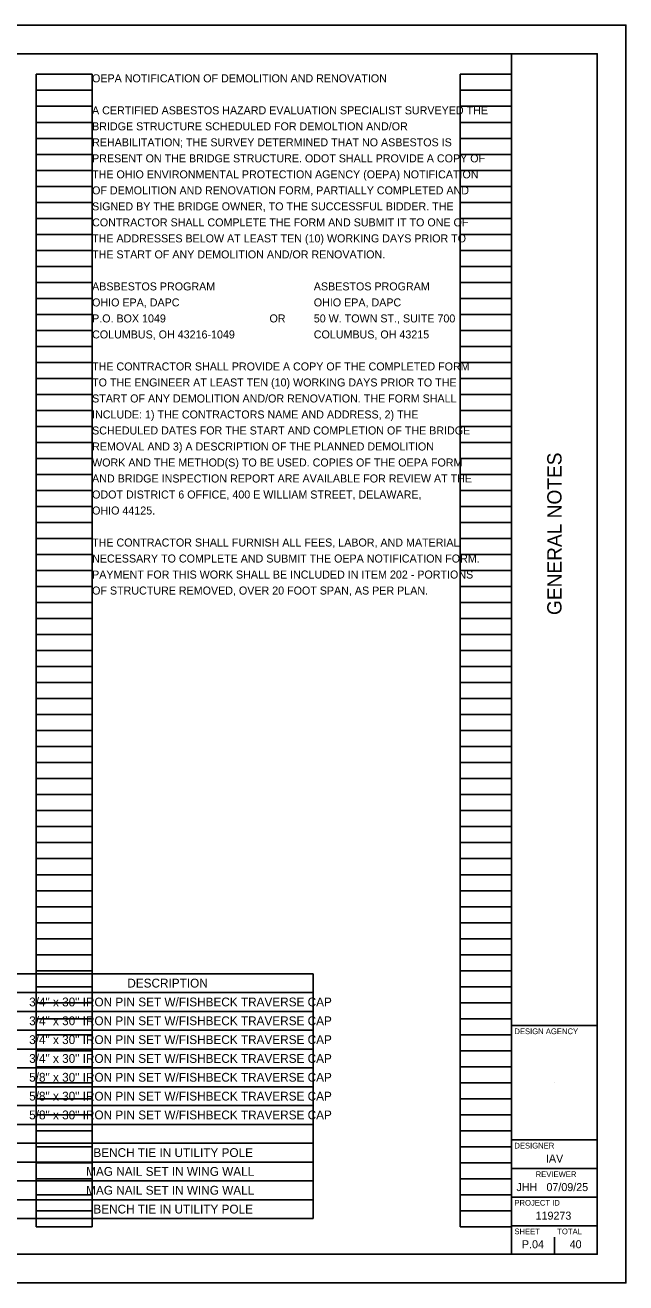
# Model space of a CAD drawing. Extents: x -10.1 to 34, y -4.5 to 22.
# Drawn here: x 23.49 to 34, y 0 to 22 of the extents above; entities that cross this region are included whole.
import ezdxf

# ---------------------------------------------------------------- set-up
doc = ezdxf.new("R2010")
doc.units = 0
for name, color, linetype in [('Default', 7, 'Continuous'), ('SH_Border', 7, 'Continuous'), ('SH_Cut_Line', 7, 'Continuous'), ('SH_Data', 7, 'Continuous'), ('SH_Text', 7, 'Continuous')]:
    doc.layers.add(name, color=color, linetype=linetype)

msp = doc.modelspace()

# ---------------------------------------------------------------- linework, layer by layer
at = {"layer": 'Default'}
for p, q in [((18.251, 5.407), (28.529, 5.407)), ((28.529, 5.407), (28.529, 1.125)), ((18.251, 5.078), (28.529, 5.078)), ((18.251, 4.749), (28.529, 4.749)), ((18.251, 4.419), (28.529, 4.419)), ((18.251, 4.09), (28.529, 4.09)), ((18.251, 3.76), (28.529, 3.76)), ((18.251, 3.431), (28.529, 3.431)), ((18.251, 3.102), (28.529, 3.102)), ((18.251, 2.772), (28.529, 2.772)), ((18.251, 2.443), (28.529, 2.443)), ((18.251, 2.113), (28.529, 2.113)), ((18.251, 1.784), (28.529, 1.784)), ((18.251, 1.454), (28.529, 1.454)), ((18.251, 1.125), (28.529, 1.125))]:
    msp.add_line(p, q, dxfattribs=at)
at = {"layer": 'SH_Cut_Line'}
for p, q in [((23.68, 0.98), (23.68, 21.14)), ((23.68, 21.14), (24.66, 21.14)), ((24.66, 0.98), (24.66, 21.14)), ((31.1, 0.98), (31.1, 21.14)), ((31.1, 21.14), (32, 21.14)), ((32, 0.98), (32, 21.14)), ((23.68, 20.86), (24.66, 20.86)), ((31.1, 20.86), (32, 20.86)), ((23.68, 20.58), (24.66, 20.58)), ((31.1, 20.58), (32, 20.58)), ((23.68, 20.3), (24.66, 20.3)), ((31.1, 20.3), (32, 20.3)), ((23.68, 20.02), (24.66, 20.02)), ((31.1, 20.02), (32, 20.02)), ((23.68, 19.74), (24.66, 19.74)), ((31.1, 19.74), (32, 19.74)), ((23.68, 19.46), (24.66, 19.46)), ((31.1, 19.46), (32, 19.46)), ((23.68, 19.18), (24.66, 19.18)), ((31.1, 19.18), (32, 19.18)), ((23.68, 18.9), (24.66, 18.9)), ((31.1, 18.9), (32, 18.9)), ((23.68, 18.62), (24.66, 18.62)), ((31.1, 18.62), (32, 18.62)), ((23.68, 18.34), (24.66, 18.34)), ((31.1, 18.34), (32, 18.34)), ((23.68, 18.06), (24.66, 18.06)), ((31.1, 18.06), (32, 18.06)), ((23.68, 17.78), (24.66, 17.78)), ((31.1, 17.78), (32, 17.78)), ((23.68, 17.5), (24.66, 17.5)), ((31.1, 17.5), (32, 17.5)), ((23.68, 17.22), (24.66, 17.22)), ((31.1, 17.22), (32, 17.22)), ((23.68, 16.94), (24.66, 16.94)), ((31.1, 16.94), (32, 16.94)), ((23.68, 16.66), (24.66, 16.66)), ((31.1, 16.66), (32, 16.66)), ((23.68, 16.38), (24.66, 16.38)), ((31.1, 16.38), (32, 16.38)), ((23.68, 16.1), (24.66, 16.1)), ((31.1, 16.1), (32, 16.1)), ((23.68, 15.82), (24.66, 15.82)), ((31.1, 15.82), (32, 15.82)), ((23.68, 15.54), (24.66, 15.54)), ((31.1, 15.54), (32, 15.54)), ((23.68, 15.26), (24.66, 15.26)), ((31.1, 15.26), (32, 15.26)), ((23.68, 14.98), (24.66, 14.98)), ((31.1, 14.98), (32, 14.98)), ((23.68, 14.7), (24.66, 14.7)), ((31.1, 14.7), (32, 14.7)), ((23.68, 14.42), (24.66, 14.42)), ((31.1, 14.42), (32, 14.42)), ((23.68, 14.14), (24.66, 14.14)), ((31.1, 14.14), (32, 14.14)), ((23.68, 13.86), (24.66, 13.86)), ((31.1, 13.86), (32, 13.86)), ((23.68, 13.58), (24.66, 13.58)), ((31.1, 13.58), (32, 13.58)), ((23.68, 13.3), (24.66, 13.3)), ((31.1, 13.3), (32, 13.3)), ((23.68, 13.02), (24.66, 13.02)), ((31.1, 13.02), (32, 13.02)), ((23.68, 12.74), (24.66, 12.74)), ((31.1, 12.74), (32, 12.74)), ((23.68, 12.46), (24.66, 12.46)), ((31.1, 12.46), (32, 12.46)), ((23.68, 12.18), (24.66, 12.18)), ((31.1, 12.18), (32, 12.18)), ((23.68, 11.9), (24.66, 11.9)), ((31.1, 11.9), (32, 11.9)), ((23.68, 11.62), (24.66, 11.62)), ((31.1, 11.62), (32, 11.62)), ((23.68, 11.34), (24.66, 11.34)), ((31.1, 11.34), (32, 11.34)), ((23.68, 11.06), (24.66, 11.06)), ((31.1, 11.06), (32, 11.06)), ((23.68, 10.78), (24.66, 10.78)), ((31.1, 10.78), (32, 10.78)), ((23.68, 10.5), (24.66, 10.5)), ((31.1, 10.5), (32, 10.5)), ((23.68, 10.22), (24.66, 10.22)), ((31.1, 10.22), (32, 10.22)), ((23.68, 9.94), (24.66, 9.94)), ((31.1, 9.94), (32, 9.94)), ((23.68, 9.66), (24.66, 9.66)), ((31.1, 9.66), (32, 9.66)), ((23.68, 9.38), (24.66, 9.38)), ((31.1, 9.38), (32, 9.38)), ((23.68, 9.1), (24.66, 9.1)), ((31.1, 9.1), (32, 9.1)), ((23.68, 8.82), (24.66, 8.82)), ((31.1, 8.82), (32, 8.82)), ((23.68, 8.54), (24.66, 8.54)), ((31.1, 8.54), (32, 8.54)), ((23.68, 8.26), (24.66, 8.26)), ((31.1, 8.26), (32, 8.26)), ((23.68, 7.98), (24.66, 7.98)), ((31.1, 7.98), (32, 7.98)), ((23.68, 7.7), (24.66, 7.7)), ((31.1, 7.7), (32, 7.7)), ((23.68, 7.42), (24.66, 7.42)), ((31.1, 7.42), (32, 7.42)), ((23.68, 7.14), (24.66, 7.14)), ((31.1, 7.14), (32, 7.14)), ((23.68, 6.86), (24.66, 6.86)), ((31.1, 6.86), (32, 6.86)), ((23.68, 6.58), (24.66, 6.58)), ((31.1, 6.58), (32, 6.58)), ((23.68, 6.3), (24.66, 6.3)), ((31.1, 6.3), (32, 6.3)), ((23.68, 6.02), (24.66, 6.02)), ((31.1, 6.02), (32, 6.02)), ((23.68, 5.74), (24.66, 5.74)), ((31.1, 5.74), (32, 5.74)), ((23.68, 5.46), (24.66, 5.46)), ((31.1, 5.46), (32, 5.46)), ((23.68, 5.18), (24.66, 5.18)), ((31.1, 5.18), (32, 5.18)), ((23.68, 4.9), (24.66, 4.9)), ((31.1, 4.9), (32, 4.9)), ((23.68, 4.62), (24.66, 4.62)), ((31.1, 4.62), (32, 4.62)), ((23.68, 4.34), (24.66, 4.34)), ((31.1, 4.34), (32, 4.34)), ((23.68, 4.06), (24.66, 4.06)), ((31.1, 4.06), (32, 4.06)), ((23.68, 3.78), (24.66, 3.78)), ((31.1, 3.78), (32, 3.78)), ((23.68, 3.5), (24.66, 3.5)), ((31.1, 3.5), (32, 3.5)), ((32.75, 3.5), (32.75, 3.5)), ((23.68, 3.22), (24.66, 3.22)), ((31.1, 3.22), (32, 3.22)), ((23.68, 2.94), (24.66, 2.94)), ((31.1, 2.94), (32, 2.94)), ((23.68, 2.66), (24.66, 2.66)), ((31.1, 2.66), (32, 2.66)), ((23.68, 2.38), (24.66, 2.38)), ((31.1, 2.38), (32, 2.38)), ((23.68, 2.1), (24.66, 2.1)), ((31.1, 2.1), (32, 2.1)), ((23.68, 1.82), (24.66, 1.82)), ((31.1, 1.82), (32, 1.82)), ((23.68, 1.54), (24.66, 1.54)), ((31.1, 1.54), (32, 1.54)), ((23.68, 1.26), (24.66, 1.26)), ((31.1, 1.26), (32, 1.26)), ((23.68, 0.98), (24.66, 0.98)), ((31.1, 0.98), (32, 0.98)), ((32.375, 0.675), (32.375, 0.675)), ((32.75, 0.5), (32.75, 0.8))]:
    msp.add_line(p, q, dxfattribs=at)
at = {"layer": 'SH_Data'}
for p, q in [((32, 0.5), (32, 21.5)), ((32, 4.5), (33.5, 4.5)), ((32, 2.5), (33.5, 2.5)), ((32, 2), (33.5, 2)), ((32, 1.5), (33.5, 1.5)), ((32, 1), (33.5, 1))]:
    msp.add_line(p, q, dxfattribs=at)
msp.add_lwpolyline([(1.5, 21.5), (33.5, 21.5), (33.5, 0.5), (1.5, 0.5)], close=True, dxfattribs=at)
at = {"layer": 'SH_Text'}
msp.add_lwpolyline([(0, 0), (34, 0), (34, 22), (0, 22)], close=True, dxfattribs=at)

# ---------------------------------------------------------------- texts
at = {"layer": 'Default'}
for s, p in [('DESCRIPTION', (25.277, 5.166)), ('3/4" x 30" IRON PIN SET W/FISHBECK TRAVERSE CAP', (23.56, 4.836)), ('3/4" x 30" IRON PIN SET W/FISHBECK TRAVERSE CAP', (23.56, 4.507)), ('3/4" x 30" IRON PIN SET W/FISHBECK TRAVERSE CAP', (23.56, 4.177)), ('3/4" x 30" IRON PIN SET W/FISHBECK TRAVERSE CAP', (23.56, 3.848)), ('5/8" x 30" IRON PIN SET W/FISHBECK TRAVERSE CAP', (23.56, 3.519)), ('5/8" x 30" IRON PIN SET W/FISHBECK TRAVERSE CAP', (23.56, 3.189)), ('5/8" x 30" IRON PIN SET W/FISHBECK TRAVERSE CAP', (23.56, 2.86)), ('BENCH TIE IN UTILITY POLE', (24.684, 2.201)), ('MAG NAIL SET IN WING WALL', (24.557, 1.872)), ('MAG NAIL SET IN WING WALL', (24.557, 1.542)), ('BENCH TIE IN UTILITY POLE', (24.684, 1.213))]:
    msp.add_text(s, height=0.154, dxfattribs=at).set_placement(p)
at = {"layer": 'SH_Border'}
for s, p in [('OEPA NOTIFICATION OF DEMOLITION AND RENOVATION', (24.66, 21)), ('A CERTIFIED ASBESTOS HAZARD EVALUATION SPECIALIST SURVEYED THE ', (24.66, 20.44)), ('BRIDGE STRUCTURE SCHEDULED FOR DEMOLTION AND/OR ', (24.661, 20.16)), ('REHABILITATION; THE SURVEY DETERMINED THAT NO ASBESTOS IS ', (24.661, 19.88)), ('PRESENT ON THE BRIDGE STRUCTURE. ODOT SHALL PROVIDE A COPY OF ', (24.661, 19.6)), ('THE OHIO ENVIRONMENTAL PROTECTION AGENCY (OEPA) NOTIFICATION ', (24.661, 19.32)), ('OF DEMOLITION AND RENOVATION FORM, PARTIALLY COMPLETED AND ', (24.661, 19.04)), ('SIGNED BY THE BRIDGE OWNER, TO THE SUCCESSFUL BIDDER. THE ', (24.661, 18.76)), ('CONTRACTOR SHALL COMPLETE THE FORM AND SUBMIT IT TO ONE OF ', (24.661, 18.48)), ('THE ADDRESSES BELOW AT LEAST TEN (10) WORKING DAYS PRIOR TO ', (24.661, 18.2)), ('THE START OF ANY DEMOLITION AND/OR RENOVATION.', (24.661, 17.92)), ('ABSBESTOS PROGRAM', (24.661, 17.36)), ('ASBESTOS PROGRAM', (28.54, 17.36)), ('OHIO EPA, DAPC', (24.661, 17.08)), ('OHIO EPA, DAPC', (28.54, 17.08)), ('P.O. BOX 1049', (24.661, 16.8)), ('OR', (27.765, 16.8)), ('50 W. TOWN ST., SUITE 700', (28.54, 16.8)), ('COLUMBUS, OH 43216-1049', (24.661, 16.52)), ('COLUMBUS, OH 43215', (28.54, 16.52)), ('THE CONTRACTOR SHALL PROVIDE A COPY OF THE COMPLETED FORM ', (24.661, 15.96)), ('TO THE ENGINEER AT LEAST TEN (10) WORKING DAYS PRIOR TO THE ', (24.661, 15.68)), ('START OF ANY DEMOLITION AND/OR RENOVATION. THE FORM SHALL ', (24.661, 15.4)), ('INCLUDE: 1) THE CONTRACTORS NAME AND ADDRESS, 2) THE ', (24.661, 15.12)), ('SCHEDULED DATES FOR THE START AND COMPLETION OF THE BRIDGE ', (24.661, 14.84)), ('REMOVAL AND 3) A DESCRIPTION OF THE PLANNED DEMOLITION ', (24.661, 14.56)), ('WORK AND THE METHOD(S) TO BE USED. COPIES OF THE OEPA FORM ', (24.661, 14.28)), ('AND BRIDGE INSPECTION REPORT ARE AVAILABLE FOR REVIEW AT THE ', (24.661, 14)), ('ODOT DISTRICT 6 OFFICE, 400 E WILLIAM STREET, DELAWARE,', (24.661, 13.72)), ('OHIO 44125.', (24.661, 13.44)), ('THE CONTRACTOR SHALL FURNISH ALL FEES, LABOR, AND MATERIAL ', (24.661, 12.88)), ('NECESSARY TO COMPLETE AND SUBMIT THE OEPA NOTIFICATION FORM. ', (24.661, 12.6)), ('PAYMENT FOR THIS WORK SHALL BE INCLUDED IN ITEM 202\xa0-\xa0PORTIONS ', (24.661, 12.32)), ('OF STRUCTURE REMOVED, OVER 20 FOOT SPAN, AS PER PLAN.', (24.661, 12.04))]:
    msp.add_text(s, height=0.14, dxfattribs=at).set_placement(p)
at = {"layer": 'SH_Cut_Line'}
msp.add_text('GENERAL NOTES', height=0.25, rotation=90, dxfattribs=at).set_placement((32.875, 11.682))
for s, height, p in [('DESIGN AGENCY', 0.1, (32.05, 4.35)), ('DESIGNER', 0.1, (32.05, 2.35)), ('IAV', 0.14, (32.602, 2.105)), ('REVIEWER', 0.1, (32.422, 1.85)), ('JHH', 0.14, (32.087, 1.605)), ('07/09/25', 0.14, (32.611, 1.605)), ('PROJECT ID', 0.1, (32.05, 1.35)), ('119273', 0.14, (32.421, 1.105)), ('SHEET', 0.1, (32.05, 0.85)), ('TOTAL', 0.1, (32.8, 0.85)), ('P.04', 0.14, (32.182, 0.605)), ('40', 0.14, (33.017, 0.605))]:
    msp.add_text(s, height=height, dxfattribs=at).set_placement(p)

doc.saveas('drawing.dxf')
